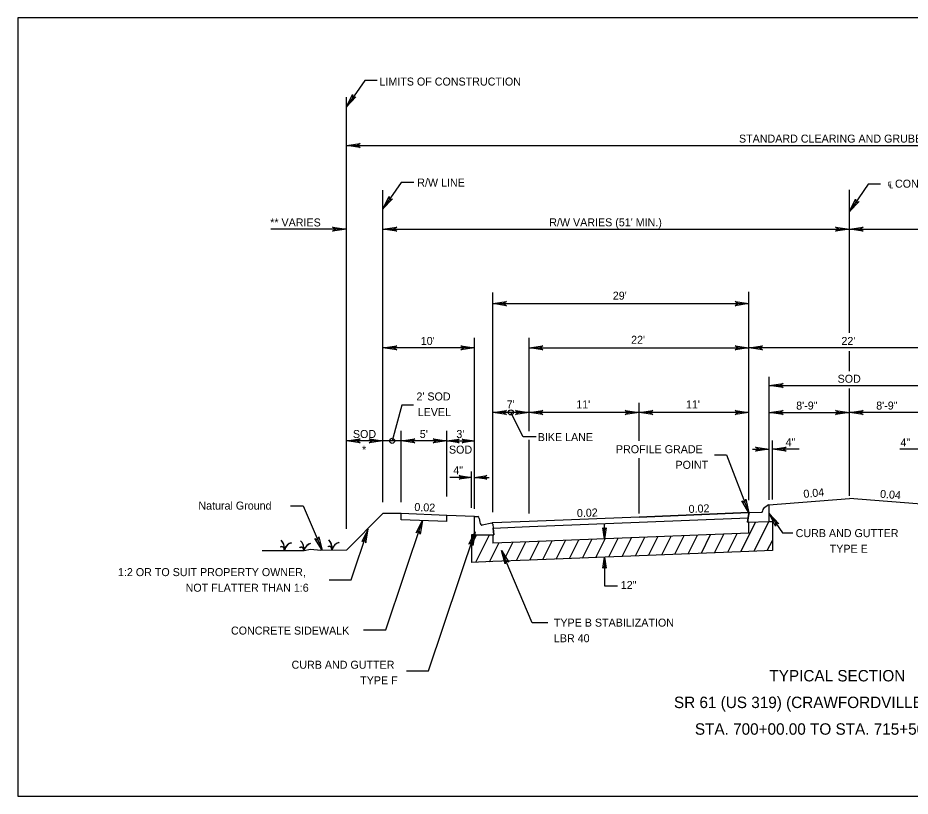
# Model space of a CAD drawing. Extents: x 1477 to 1648, y 601 to 679.
# Drawn here: x 1476.9 to 1566.4, y 600.9 to 679 of the extents above; entities that cross this region are included whole.
import ezdxf

# ---------------------------------------------------------------- set-up
doc = ezdxf.new("R2010")
doc.units = 0
for name, color, linetype in [('CandG_px', 7, 'Continuous'), ('CLConst_dp', 7, 'Continuous'), ('ClipDrawingBound_dp', 7, 'Continuous'), ('ConstLimits', 7, 'Continuous'), ('DimLines_dp', 7, 'Continuous'), ('LeaderLine_dp', 7, 'Continuous'), ('PavtBase_px', 7, 'Continuous'), ('PavtMisc', 7, 'Continuous'), ('PavtStabilization', 7, 'Continuous'), ('RWLine', 7, 'Continuous'), ('Sidewalk_px', 7, 'Continuous'), ('Sod', 7, 'Continuous'), ('TextMisc', 7, 'Continuous'), ('TextTitle', 7, 'Continuous'), ('XSTypical_px', 7, 'Continuous')]:
    doc.layers.add(name, color=color, linetype=linetype)

msp = doc.modelspace()

# ---------------------------------------------------------------- linework, layer by layer
at = {"layer": 'CandG_px'}
for p, q in [((1552.183, 630.121), (1551.678, 629.784)), ((1552.271, 628.471), (1552.271, 630.048)), ((1522.709, 627.127), (1522.709, 628.963)), ((1522.709, 628.963), (1523.058, 628.963)), ((1550.216, 629.264), (1550.088, 628.405)), ((1551.524, 629.378), (1550.276, 629.329)), ((1551.584, 629.521), (1551.584, 629.5)), ((1523.202, 628.753), (1523.262, 628.39)), ((1524.471, 628.287), (1523.502, 628.081)), ((1524.542, 628.206), (1524.587, 627.811)), ((1550.088, 628.405), (1552.271, 628.471)), ((1522.709, 627.127), (1524.664, 627.127)), ((1524.587, 627.811), (1524.664, 627.127))]:
    msp.add_line(p, q, dxfattribs=at)
for centre, major_axis, ratio, start_param, end_param in [((1551.721, 629.522), (0, 0.275), 0.499226, 0.321751, 1.570796), ((1552.21, 630.047), (0, 0.0816), 0.748839, 4.712389, 6.747614), ((1523.057, 628.657), (0, 0.306), 0.499226, 5.03414, 6.283185), ((1550.278, 629.248), (0, 0.0816), 0.748839, 0.034186, 1.375361), ((1551.523, 629.501), (0, -0.122), 0.499226, 0.021273, 1.570796), ((1523.479, 628.538), (0, -0.459), 0.499226, 5.037885, 6.382854), ((1524.481, 628.206), (0, 0.0816), 0.748839, 4.713335, 6.4444), ((1524.481, 628.206), (0, 0.0816), 0.748839, 4.712752, 6.4444)]:
    msp.add_ellipse(centre, major_axis=major_axis, ratio=ratio, start_param=start_param, end_param=end_param, dxfattribs=at)
at = {"layer": 'CLConst_dp'}
for p, q in [((1560.292, 647.392), (1560.292, 661.741)), ((1560.292, 643.533), (1560.292, 645.545)), ((1560.292, 631.045), (1560.292, 641.804))]:
    msp.add_line(p, q, dxfattribs=at)
at = {"layer": 'ClipDrawingBound_dp'}
msp.add_lwpolyline([(1476.944, 678.987), (1476.944, 600.914), (1647.602, 600.914), (1647.602, 678.987)], close=True, dxfattribs=at)
at = {"layer": 'ConstLimits'}
msp.add_line((1509.875, 627.742), (1509.875, 671.034), dxfattribs=at)
at = {"layer": 'DimLines_dp'}
for p, q in [((1509.875, 666.184), (1610.709, 666.184)), ((1509.875, 657.789), (1502.307, 657.789)), ((1513.542, 657.789), (1560.292, 657.789)), ((1560.292, 657.789), (1607.042, 657.789)), ((1524.542, 629.397), (1524.542, 651.439)), ((1550.209, 630.597), (1550.209, 651.503)), ((1524.542, 650.316), (1550.209, 650.316)), ((1522.709, 629.719), (1522.709, 646.898)), ((1528.209, 637.536), (1528.209, 646.898)), ((1528.209, 645.888), (1550.209, 645.888)), ((1570.377, 645.888), (1550.209, 645.888)), ((1552.271, 630.637), (1552.271, 642.978)), ((1552.271, 642.096), (1568.311, 642.096)), ((1539.209, 636.568), (1539.209, 640.376)), ((1528.209, 639.406), (1524.542, 639.406)), ((1539.209, 639.406), (1528.209, 639.406)), ((1550.209, 639.406), (1539.209, 639.406)), ((1552.271, 639.406), (1560.292, 639.406)), ((1568.313, 639.406), (1560.292, 639.406)), ((1515.375, 630.41), (1515.375, 637.553)), ((1519.959, 630.976), (1519.959, 637.553)), ((1513.542, 636.554), (1509.875, 636.554)), ((1515.375, 636.554), (1513.542, 636.554)), ((1519.959, 636.554), (1515.375, 636.554)), ((1519.959, 636.554), (1522.709, 636.554)), ((1528.209, 629.277), (1528.209, 636.655)), ((1552.577, 630.679), (1552.577, 636.592)), ((1550.572, 635.728), (1552.271, 635.728)), ((1555.25, 635.728), (1552.577, 635.728)), ((1568.006, 635.727), (1565.353, 635.727)), ((1539.209, 629.278), (1539.209, 634.822)), ((1522.404, 629.823), (1522.404, 633.476)), ((1522.404, 632.895), (1520.238, 632.895)), ((1522.709, 632.895), (1524.173, 632.895)), ((1552.271, 629.259), (1553.603, 627.318)), ((1535.76, 626.729), (1535.76, 628.156)), ((1553.603, 627.318), (1554.631, 627.318))]:
    msp.add_line(p, q, dxfattribs=at)
for points in [[(1512.975, 672.7), (1511.709, 672.7), (1509.875, 670.066)], [(1516.641, 662.459), (1515.375, 662.459), (1513.542, 659.825)], [(1563.401, 662.312), (1562.185, 662.312), (1560.323, 659.549)], [(1516.604, 640.145), (1515.432, 640.145), (1514.451, 636.557)], [(1528.905, 636.952), (1527.612, 636.952), (1526.377, 639.404)], [(1546.765, 635.146), (1547.993, 635.146), (1550.209, 629.332)], [(1504.265, 630.028), (1505.55, 630.028), (1507.453, 625.583)], [(1511.608, 617.591), (1513.826, 617.591), (1517.514, 628.56)], [(1508.134, 622.605), (1510.352, 622.605), (1512.067, 627.705)], [(1515.897, 613.49), (1518.115, 613.49), (1522.8, 627.425)], [(1530.083, 618.313), (1528.511, 618.313), (1525.429, 625.559)], [(1535.76, 624.891), (1535.76, 621.997), (1537.055, 622.004)]]:
    msp.add_lwpolyline(points, dxfattribs=at)
at = {"layer": 'LeaderLine_dp'}
for p, q in [((1509.875, 670.066), (1510.492, 671.312)), ((1510.83, 671.077), (1509.875, 670.066)), ((1510.492, 671.312), (1510.504, 670.969)), ((1510.504, 670.969), (1510.83, 671.077)), ((1509.875, 666.184), (1511.25, 666.391)), ((1511.25, 666.391), (1510.975, 666.184)), ((1511.25, 665.978), (1509.875, 666.184)), ((1510.975, 666.184), (1511.25, 665.978)), ((1513.542, 659.825), (1514.158, 661.071)), ((1514.158, 661.071), (1514.17, 660.728)), ((1514.497, 660.836), (1513.542, 659.825)), ((1514.17, 660.728), (1514.497, 660.836)), ((1560.323, 659.549), (1560.921, 660.805)), ((1561.263, 660.574), (1560.323, 659.549)), ((1560.921, 660.805), (1560.938, 660.461)), ((1560.938, 660.461), (1561.263, 660.574)), ((1508.775, 657.789), (1508.5, 657.995)), ((1508.5, 657.995), (1509.875, 657.789)), ((1509.875, 657.789), (1508.5, 657.583)), ((1508.5, 657.583), (1508.775, 657.789)), ((1513.542, 657.789), (1514.917, 657.995)), ((1514.917, 657.583), (1513.542, 657.789)), ((1514.917, 657.995), (1514.642, 657.789)), ((1514.642, 657.789), (1514.917, 657.583)), ((1559.192, 657.789), (1558.917, 657.995)), ((1558.917, 657.995), (1560.292, 657.789)), ((1560.292, 657.789), (1558.917, 657.583)), ((1558.917, 657.583), (1559.192, 657.789)), ((1560.292, 657.789), (1561.667, 657.995)), ((1561.667, 657.583), (1560.292, 657.789)), ((1561.667, 657.995), (1561.392, 657.789)), ((1561.392, 657.789), (1561.667, 657.583)), ((1524.542, 650.316), (1525.917, 650.523)), ((1525.917, 650.11), (1524.542, 650.316)), ((1525.917, 650.523), (1525.642, 650.316)), ((1525.642, 650.316), (1525.917, 650.11)), ((1549.109, 650.316), (1548.834, 650.523)), ((1548.834, 650.523), (1550.209, 650.316)), ((1550.209, 650.316), (1548.834, 650.11)), ((1548.834, 650.11), (1549.109, 650.316)), ((1513.542, 645.888), (1514.917, 646.095)), ((1514.917, 645.682), (1513.542, 645.888)), ((1514.917, 646.095), (1514.642, 645.888)), ((1514.642, 645.888), (1514.917, 645.682)), ((1521.609, 645.888), (1521.334, 646.095)), ((1521.334, 646.095), (1522.709, 645.888)), ((1522.709, 645.888), (1521.334, 645.682)), ((1521.334, 645.682), (1521.609, 645.888)), ((1528.209, 645.888), (1529.584, 646.095)), ((1529.584, 645.682), (1528.209, 645.888)), ((1529.584, 646.095), (1529.309, 645.888)), ((1529.309, 645.888), (1529.584, 645.682)), ((1549.109, 645.888), (1548.834, 646.095)), ((1548.834, 646.095), (1550.209, 645.888)), ((1550.209, 645.888), (1548.834, 645.682)), ((1548.834, 645.682), (1549.109, 645.888)), ((1550.209, 645.888), (1551.584, 646.095)), ((1551.584, 645.682), (1550.209, 645.888)), ((1551.584, 646.095), (1551.309, 645.888)), ((1551.309, 645.888), (1551.584, 645.682)), ((1552.271, 642.096), (1553.646, 642.302)), ((1553.646, 642.302), (1553.371, 642.096)), ((1553.646, 641.89), (1552.271, 642.096)), ((1553.371, 642.096), (1553.646, 641.89)), ((1524.542, 639.406), (1525.917, 639.612)), ((1525.917, 639.612), (1525.642, 639.406)), ((1527.109, 639.406), (1526.834, 639.612)), ((1526.834, 639.612), (1528.209, 639.406)), ((1528.209, 639.406), (1529.584, 639.612)), ((1529.584, 639.612), (1529.309, 639.406)), ((1538.109, 639.406), (1537.834, 639.612)), ((1537.834, 639.612), (1539.209, 639.406)), ((1539.209, 639.406), (1540.584, 639.612)), ((1540.584, 639.612), (1540.309, 639.406)), ((1549.109, 639.406), (1548.834, 639.612)), ((1548.834, 639.612), (1550.209, 639.406)), ((1552.271, 639.406), (1553.646, 639.612)), ((1553.646, 639.612), (1553.371, 639.406)), ((1559.192, 639.406), (1558.917, 639.612)), ((1558.917, 639.612), (1560.292, 639.406)), ((1560.292, 639.406), (1561.667, 639.612)), ((1561.667, 639.612), (1561.392, 639.406)), ((1525.917, 639.2), (1524.542, 639.406)), ((1525.642, 639.406), (1525.917, 639.2)), ((1528.209, 639.406), (1526.834, 639.2)), ((1526.834, 639.2), (1527.109, 639.406)), ((1529.584, 639.2), (1528.209, 639.406)), ((1529.309, 639.406), (1529.584, 639.2)), ((1539.209, 639.406), (1537.834, 639.2)), ((1537.834, 639.2), (1538.109, 639.406)), ((1540.584, 639.2), (1539.209, 639.406)), ((1540.309, 639.406), (1540.584, 639.2)), ((1550.209, 639.406), (1548.834, 639.2)), ((1548.834, 639.2), (1549.109, 639.406)), ((1553.646, 639.2), (1552.271, 639.406)), ((1553.371, 639.406), (1553.646, 639.2)), ((1560.292, 639.406), (1558.917, 639.2)), ((1558.917, 639.2), (1559.192, 639.406)), ((1561.667, 639.2), (1560.292, 639.406)), ((1561.392, 639.406), (1561.667, 639.2)), ((1509.875, 636.554), (1511.25, 636.76)), ((1511.25, 636.348), (1509.875, 636.554)), ((1511.25, 636.76), (1510.975, 636.554)), ((1510.975, 636.554), (1511.25, 636.348)), ((1512.442, 636.554), (1512.167, 636.76)), ((1512.167, 636.76), (1513.542, 636.554)), ((1513.542, 636.554), (1512.167, 636.348)), ((1512.167, 636.348), (1512.442, 636.554)), ((1515.375, 636.554), (1516.75, 636.76)), ((1516.75, 636.348), (1515.375, 636.554)), ((1516.75, 636.76), (1516.475, 636.554)), ((1516.475, 636.554), (1516.75, 636.348)), ((1518.859, 636.554), (1518.584, 636.76)), ((1518.584, 636.76), (1519.959, 636.554)), ((1519.959, 636.554), (1518.584, 636.348)), ((1518.584, 636.348), (1518.859, 636.554)), ((1519.959, 636.554), (1521.196, 636.74)), ((1521.196, 636.368), (1519.959, 636.554)), ((1521.196, 636.74), (1520.949, 636.554)), ((1520.949, 636.554), (1521.196, 636.368)), ((1521.719, 636.554), (1521.471, 636.74)), ((1521.471, 636.74), (1522.709, 636.554)), ((1522.709, 636.554), (1521.471, 636.368)), ((1521.471, 636.368), (1521.719, 636.554)), ((1551.171, 635.728), (1550.896, 635.934)), ((1550.896, 635.934), (1552.271, 635.728)), ((1552.271, 635.728), (1550.896, 635.522)), ((1550.896, 635.522), (1551.171, 635.728)), ((1552.577, 635.728), (1553.952, 635.934)), ((1553.952, 635.522), (1552.577, 635.728)), ((1553.952, 635.934), (1553.677, 635.728)), ((1553.677, 635.728), (1553.952, 635.522)), ((1521.414, 632.895), (1521.166, 633.08)), ((1521.166, 633.08), (1522.404, 632.895)), ((1522.404, 632.895), (1521.166, 632.709)), ((1521.166, 632.709), (1521.414, 632.895)), ((1522.709, 632.895), (1523.946, 633.08)), ((1523.946, 632.709), (1522.709, 632.895)), ((1523.946, 633.08), (1523.699, 632.895)), ((1523.699, 632.895), (1523.946, 632.709)), ((1549.817, 630.36), (1549.912, 630.69)), ((1549.912, 630.69), (1550.209, 629.332)), ((1550.209, 629.332), (1549.526, 630.543)), ((1549.526, 630.543), (1549.817, 630.36)), ((1552.271, 629.259), (1553.219, 628.242)), ((1552.879, 628.009), (1552.271, 629.259)), ((1516.88, 627.322), (1517.514, 628.56)), ((1517.514, 628.56), (1517.271, 627.191)), ((1552.894, 628.352), (1552.879, 628.009)), ((1553.219, 628.242), (1552.894, 628.352)), ((1512.067, 627.705), (1511.433, 626.468)), ((1511.824, 626.336), (1512.067, 627.705)), ((1517.163, 627.517), (1516.88, 627.322)), ((1517.271, 627.191), (1517.163, 627.517)), ((1522.166, 626.187), (1522.8, 627.425)), ((1522.8, 627.425), (1522.557, 626.056)), ((1535.76, 626.729), (1535.595, 627.829)), ((1535.595, 627.829), (1535.76, 627.609)), ((1535.76, 627.609), (1535.925, 627.829)), ((1535.925, 627.829), (1535.76, 626.729)), ((1507.453, 625.583), (1506.722, 626.766)), ((1506.722, 626.766), (1507.02, 626.595)), ((1507.02, 626.595), (1507.101, 626.929)), ((1507.101, 626.929), (1507.453, 625.583)), ((1511.433, 626.468), (1511.716, 626.663)), ((1511.716, 626.663), (1511.824, 626.336)), ((1522.449, 626.382), (1522.166, 626.187)), ((1522.557, 626.056), (1522.449, 626.382)), ((1525.429, 625.559), (1526.157, 624.374)), ((1525.778, 624.213), (1525.429, 625.559)), ((1525.86, 624.546), (1525.778, 624.213)), ((1526.157, 624.374), (1525.86, 624.546)), ((1535.595, 623.791), (1535.76, 624.891)), ((1535.76, 624.891), (1535.925, 623.791)), ((1535.76, 624.011), (1535.595, 623.791)), ((1535.925, 623.791), (1535.76, 624.011))]:
    msp.add_line(p, q, dxfattribs=at)
at = {"layer": 'PavtBase_px'}
for p, q in [((1550.088, 628.405), (1550.152, 628.834)), ((1550.209, 628.409), (1550.088, 628.405)), ((1550.201, 627.306), (1550.209, 628.409)), ((1524.542, 627.123), (1524.664, 627.127)), ((1524.542, 627.123), (1524.542, 626.275)), ((1524.664, 627.127), (1524.587, 627.811)), ((1550.201, 627.306), (1539.21, 626.866)), ((1528.209, 626.426), (1524.54, 626.279)), ((1539.21, 626.866), (1528.209, 626.426))]:
    msp.add_line(p, q, dxfattribs=at)
at = {"layer": 'PavtMisc'}
for points in [[(1550.209, 629.355), (1550.203, 629.354), (1550.209, 629.328), (1550.194, 629.355), (1539.209, 628.915), (1528.209, 628.475), (1524.542, 628.328)], [(1524.542, 628.206), (1524.587, 627.811), (1528.221, 627.957), (1539.221, 628.397), (1550.147, 628.834), (1550.153, 628.833), (1550.218, 629.263)], [(1524.471, 628.287), (1524.471, 628.287)]]:
    msp.add_lwpolyline(points, dxfattribs=at)
for centre, major_axis, start_param, end_param in [((1550.199, 629.197), (0, 0.159), 5.678138, 6.200881), ((1550.278, 629.248), (0, 0.0816), 0.179724, 1.375361), ((1524.552, 628.17), (0, 0.159), 0.082304, 0.74615), ((1524.481, 628.206), (0, 0.0816), 4.713335, 6.4444)]:
    msp.add_ellipse(centre, major_axis=major_axis, ratio=0.748839, start_param=start_param, end_param=end_param, dxfattribs=at)
at = {"layer": 'PavtStabilization'}
for p, q in [((1549.424, 625.439), (1550.918, 628.43)), ((1550.748, 625.492), (1552.234, 628.47)), ((1552.271, 628.471), (1552.577, 628.471)), ((1552.577, 628.471), (1552.577, 625.565)), ((1522.709, 627.127), (1522.404, 627.127)), ((1522.404, 627.127), (1522.404, 624.359)), ((1522.404, 626.08), (1522.926, 627.127)), ((1522.848, 624.375), (1524.222, 627.127)), ((1542.81, 625.175), (1543.745, 627.045)), ((1544.134, 625.226), (1545.068, 627.1)), ((1545.456, 625.281), (1546.391, 627.152)), ((1546.779, 625.332), (1547.714, 627.206)), ((1548.102, 625.385), (1549.036, 627.258)), ((1524.232, 624.429), (1525.166, 626.303)), ((1525.615, 624.486), (1526.549, 626.358)), ((1526.936, 624.538), (1527.871, 626.412)), ((1528.26, 624.592), (1529.194, 626.464)), ((1529.583, 624.645), (1530.517, 626.517)), ((1530.906, 624.698), (1531.841, 626.571)), ((1532.228, 624.751), (1533.162, 626.622)), ((1533.551, 624.803), (1534.486, 626.676)), ((1534.874, 624.857), (1535.809, 626.729)), ((1536.197, 624.91), (1537.131, 626.781)), ((1537.519, 624.962), (1538.454, 626.835)), ((1538.842, 625.016), (1539.777, 626.887)), ((1540.165, 625.067), (1541.1, 626.94)), ((1541.488, 625.12), (1542.423, 626.994)), ((1552.071, 625.545), (1552.577, 626.558)), ((1550.209, 625.47), (1539.211, 625.031)), ((1552.577, 625.565), (1550.209, 625.47)), ((1524.542, 624.444), (1522.404, 624.359)), ((1528.209, 624.591), (1524.542, 624.444)), ((1539.209, 625.031), (1528.209, 624.591))]:
    msp.add_line(p, q, dxfattribs=at)
at = {"layer": 'RWLine'}
msp.add_line((1513.542, 630.41), (1513.542, 661.717), dxfattribs=at)
at = {"layer": 'Sidewalk_px'}
for p, q in [((1515.363, 628.646), (1515.375, 629.256)), ((1519.959, 629.073), (1515.375, 629.256)), ((1519.946, 628.463), (1519.959, 629.073)), ((1519.946, 628.463), (1515.363, 628.646))]:
    msp.add_line(p, q, dxfattribs=at)
at = {"layer": 'Sod'}
for p, q in [((1552.227, 630.125), (1560.292, 630.771)), ((1568.358, 630.125), (1560.292, 630.771)), ((1513.542, 629.256), (1509.875, 625.584)), ((1515.375, 629.256), (1513.542, 629.256)), ((1522.709, 628.963), (1519.959, 629.073))]:
    msp.add_line(p, q, dxfattribs=at)
msp.add_lwpolyline([(1509.875, 625.584), (1507.301, 625.571), (1506.293, 625.654), (1505.635, 625.51), (1504.379, 625.53), (1502.94, 625.53), (1501.437, 625.53)], dxfattribs=at)
for centre, major_axis, ratio in [((1503.333, 626.589), (0.00348, 0.00738), 0.389816), ((1504.338, 626.31), (0.0015, -0.0123), 0.218972), ((1505.288, 626.534), (0.00348, 0.00738), 0.389816), ((1506.293, 626.254), (0.0015, -0.0123), 0.218972), ((1508.107, 626.617), (0.00348, 0.00738), 0.389816), ((1509.112, 626.337), (0.0015, -0.0123), 0.218972), ((1503.245, 625.894), (-0.00319, 0.0083), 0.334101), ((1505.2, 625.838), (-0.00319, 0.0083), 0.334101), ((1508.018, 625.921), (-0.00319, 0.0083), 0.334101)]:
    msp.add_ellipse(centre, major_axis=major_axis, ratio=ratio, dxfattribs=at)
for centre, major_axis, start_param, end_param in [((1502.94, 625.775), (0, -0.96), 1.43816, 2.57018), ((1502.94, 625.775), (0, -0.978), 1.375837, 2.57018), ((1504.456, 625.173), (0, 1.136), 0.136484, 1.211739), ((1504.456, 625.173), (0, 1.16), 0.136484, 1.135245), ((1504.895, 625.719), (0, -0.96), 1.43816, 2.57018), ((1504.895, 625.719), (0, -0.978), 1.375837, 2.57018), ((1506.411, 625.117), (0, 1.136), 0.136484, 1.211739), ((1506.411, 625.117), (0, 1.16), 0.136484, 1.135245), ((1507.714, 625.802), (0, -0.96), 1.43816, 2.57018), ((1507.714, 625.802), (0, -0.978), 1.375837, 2.57018), ((1509.229, 625.2), (0, 1.136), 0.136484, 1.211739), ((1509.229, 625.2), (0, 1.16), 0.136484, 1.135245), ((1503.386, 625.571), (0, 0.383), 5.050826, 6.812464), ((1503.386, 625.571), (0, 0.365), 4.696782, 6.812464), ((1505.341, 625.515), (0, 0.383), 5.050826, 6.812464), ((1505.341, 625.515), (0, 0.365), 4.696782, 6.812464), ((1508.16, 625.598), (0, 0.383), 5.050826, 6.812464), ((1508.16, 625.598), (0, 0.365), 4.696782, 6.812464)]:
    msp.add_ellipse(centre, major_axis=major_axis, ratio=0.748839, start_param=start_param, end_param=end_param, dxfattribs=at)
at = {"layer": 'TextMisc'}
for p, q in [((1522.709, 645.888), (1513.542, 645.888)), ((1550.217, 629.264), (1550.217, 629.264))]:
    msp.add_line(p, q, dxfattribs=at)
for centre in [(1526.375, 639.406), (1514.459, 636.554)]:
    msp.add_circle(centre, 0.255, dxfattribs=at)
at = {"layer": 'XSTypical_px'}
for p, q in [((1539.209, 628.915), (1528.209, 628.475)), ((1539.209, 628.915), (1550.209, 629.355)), ((1539.221, 628.397), (1550.152, 628.834)), ((1528.209, 628.475), (1524.542, 628.329)), ((1524.587, 627.811), (1528.221, 627.957)), ((1528.221, 627.957), (1539.221, 628.397))]:
    msp.add_line(p, q, dxfattribs=at)
for centre, start_param, end_param in [((1550.199, 629.197), 5.678138, 6.200881), ((1524.552, 628.17), 0.082304, 0.74615)]:
    msp.add_ellipse(centre, major_axis=(0, 0.159), ratio=0.748839, start_param=start_param, end_param=end_param, dxfattribs=at)

# ---------------------------------------------------------------- texts
at = {"layer": 'TextMisc'}
for s, height, p in [('LIMITS OF CONSTRUCTION', 0.80208, (1513.194, 672.193)), ('STANDARD CLEARING AND GRUBBING', 0.80208, (1549.231, 666.471)), ('R/W LINE', 0.8021, (1516.982, 662.066)), ('℄ CONST. SR 61', 0.80208, (1564.136, 661.951)), ('** VARIES', 0.8021, (1502.24, 658.062)), ("R/W VARIES (51' MIN.)", 0.80208, (1530.212, 658.076)), ("29'", 0.8021, (1536.581, 650.717)), ("10'", 0.8021, (1517.331, 646.175)), ("22'", 0.8021, (1538.414, 646.289)), ("22'", 0.8021, (1559.498, 646.175)), ('SOD', 0.8021, (1559.115, 642.383)), ("2' SOD", 0.8021, (1516.899, 640.607)), ("7'", 0.8021, (1525.941, 639.807)), ("11'", 0.8021, (1532.914, 639.807)), ("11'", 0.8021, (1543.914, 639.807)), ('8\'-9"', 0.8021, (1554.965, 639.692)), ('8\'-9"', 0.8021, (1562.986, 639.692)), ('LEVEL', 0.8021, (1517.027, 639.041)), ('SOD', 0.8021, (1510.532, 636.84)), ("3'", 0.8021, (1520.899, 636.84)), ('BIKE LANE', 0.8021, (1529.057, 636.532)), ('*', 0.802, (1511.443, 635.275)), ('SOD', 0.8021, (1520.157, 635.275)), ('PROFILE GRADE ', 0.80208, (1536.895, 635.315)), ('4"', 0.8021, (1553.9, 636.013)), ('4"', 0.8021, (1565.412, 635.995)), ('POINT', 0.8021, (1542.864, 633.749)), ('4"', 0.8021, (1520.591, 633.212)), ('Natural Ground', 0.80208, (1495.041, 629.659)), ('CURB AND GUTTER', 0.80208, (1554.91, 626.899)), ('TYPE E ', 0.8021, (1558.325, 625.333)), ('1:2 OR TO SUIT PROPERTY OWNER,', 0.80208, (1486.982, 622.987)), ('NOT FLATTER THAN 1:6', 0.80208, (1493.762, 621.421)), ('12"', 0.8021, (1537.382, 621.695)), ('TYPE B STABILIZATION', 0.80208, (1530.675, 617.92)), ('CONCRETE SIDEWALK', 0.80208, (1498.307, 617.122)), ('LBR 40', 0.8021, (1530.675, 616.354)), ('CURB AND GUTTER', 0.80208, (1504.382, 613.697)), ('TYPE F', 0.8021, (1511.26, 612.131))]:
    msp.add_text(s, height=height, dxfattribs=at).set_placement(p)
for s, rotation, p in [("5'", 357.75024, (1517.217, 636.858)), ('0.04', 5.33483, (1555.724, 630.827)), ('0.04', 355.99666, (1563.351, 630.847)), ('0.02', 357.70939, (1516.677, 629.528)), ('0.02', 2.29061, (1532.997, 628.896)), ('0.02', 2.29061, (1544.196, 629.314))]:
    msp.add_text(s, height=0.8021, rotation=rotation, dxfattribs=at).set_placement(p)
at = {"layer": 'TextTitle'}
for s, p in [('TYPICAL SECTION', (1552.278, 612.423)), ('SR 61 (US 319) (CRAWFORDVILLE HWY.)', (1542.712, 609.75)), ('STA. 700+00.00 TO STA. 715+50.00', (1544.81, 607.077))]:
    msp.add_text(s, height=1.14583, dxfattribs=at).set_placement(p)

doc.saveas('drawing.dxf')
